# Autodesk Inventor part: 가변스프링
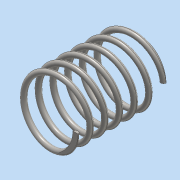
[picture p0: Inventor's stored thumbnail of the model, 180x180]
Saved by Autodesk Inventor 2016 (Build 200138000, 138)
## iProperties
Created: 2018-11
Part Number: 가변스프링
Material: 스테인레스 스틸
Document SubType Name: Modeling
Designer: user
Density: 8 g/cm^3
Appearance: 반연마
Mass: 84.213 g
Surface Area: 106.446 cm^2
Volume: 10.5266 cm^3
Author: user
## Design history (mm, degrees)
sketch "스케치2"
  geometry: L1 (0, 0)-(22.5, 0); L2 (22.5, 0)-(22.5, 67.25); L3 (22.5, 67.25)-(0, 67.25); L4 (0, 67.25)-(0, 0); C1 r 2 at (22.5, 0)
  constraints: 8 end point, 2 parallel, 1 centre point, 1 coincident, 1 horizontal, 1 perpendicular
  dimensions: "d3" = 22.5 distance of L3.end L2.end; "d4" = 67.25 distance of L2.end L1.end (derived); "d5" = 4 diameter of C1
feature "코일1" sketch "스케치2" pitch "d6" = 10; turns "d8" = 6; dims "d7" = 67.25 (= d4), "d9" = 0, angle "d10" = 90 deg, angle "d11" = 90 deg, "d12" = 0, "d13" = 0
sketch "스케치3"
  geometry: L1 (67.25, 34.625)-(0, 34.625); L2 (0, 34.625)-(0, -34.625); L3 (0, -34.625)-(67.25, -34.625); L4 (67.25, -34.625)-(67.25, 34.625); 2 further points
  constraints: 8 end point, 2 parallel, 1 coincident, 1 horizontal, 1 midpoint, 1 perpendicular
  dimensions: "d14" = 67.25 distance of L2.end L3.end (= d4); "d15" = 69.24925 distance of L3.end L1.start
extrude "돌출1" sketch "스케치3" stored distance "d16" = 100; taper "d17" = 0 deg
node "솔리드1"
